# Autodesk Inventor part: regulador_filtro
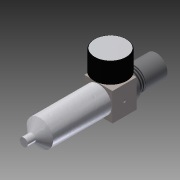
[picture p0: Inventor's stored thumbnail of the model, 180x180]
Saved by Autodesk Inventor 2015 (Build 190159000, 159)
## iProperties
Created: 2016-06
Part Number: regulador_filtro
Material: Genérico
Document SubType Name: Modeling
Designer: Diego
Density: 1 g/cm^3
Appearance: Valor por defecto
Author: Diego
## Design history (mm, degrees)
sketch "Boceto1"
  geometry: L1 (0, 0)-(35, 0); L2 (35, 0)-(35, 30); L3 (35, 30)-(0, 30); L4 (0, 30)-(0, 0)
  constraints: 8 end point, 2 parallel, 1 horizontal, 1 perpendicular
  dimensions: "d0" = 35 distance of L3.end L2.end; "d1" = 30 distance of L2.end L1.end
extrude "Extrusión1" new body sketch "Boceto1" distance "d2" = 35; taper "d3" = 0 deg
sketch "Boceto2"
  geometry: C1 r 17.534 at (17.5, -17.5); 1 further point
  constraints: 1 centre point
extrude "Extrusión2" join sketch "Boceto2" distance "d4" = 5; taper "d5" = 0 deg
sketch "Boceto3"
  geometry: C1 r 13.5 at (0, 0); 1 further point
  constraints: 1 centre point
  dimensions: "d6" = 27 diameter of C1
extrude "Extrusión3" join sketch "Boceto3" distance "d7" = 10; taper "d8" = 0 deg
feature "Rosca1" dims "d9" = 10, "d10" = 0
sketch "Boceto4"
  geometry: C1 r 14 at (0, 0); 1 further point
  constraints: 1 centre point
  dimensions: "d11" = 28 diameter of C1
extrude "Extrusión4" join sketch "Boceto4" distance "d12" = 27; taper "d13" = 0 deg
sketch "Boceto5"
  geometry: C1 r 5 at (17.5, 15); 1 further point
  constraints: 1 centre point
  dimensions: "d14" = 10 diameter of C1
extrude "Extrusión5" join sketch "Boceto5" distance "d15" = 5; taper "d16" = 0 deg
sketch "Boceto6"
  geometry: C1 r 20.5 at (0, 0); 1 further point
  constraints: 1 centre point
  dimensions: "d17" = 41 diameter of C1
extrude "Extrusión6" join sketch "Boceto6" distance "d18" = 25; taper "d19" = 0 deg
sketch "Boceto7"
  geometry: C1 r 20.5 at (0, 0) reference; C2 r 19.5 at (0, 0); 1 further point
  constraints: 1 centre point
  dimensions: "d20" = 1 radial gap between concentric circles of C1 C2
extrude "Extrusión7" join sketch "Boceto7" distance "d21" = 2; taper "d22" = 0 deg
fillet "Empalme1" dims "d23" = 2
sketch "Boceto8"
  geometry: 2 further points
hole "Agujero1" sketch "Boceto8" at (16.415, 15) diameter "d24" = 3; stored, may be unused: countersink angle "d28" = 90 deg, drill point angle "d30" = 118 deg; dims "d25" = 6, "d26" = 4, "d27" = 2, "d29" = 1
sketch "Boceto9"
  geometry: 2 further points
hole "Agujero2" sketch "Boceto9" at (-16.415, 15) diameter "d31" = 3; stored, may be unused: countersink angle "d35" = 90 deg, drill point angle "d37" = 118 deg; dims "d32" = 6, "d33" = 4, "d34" = 2, "d36" = 1
sketch "Boceto10"
  geometry: C1 r 13.5 at (17.5, 17.5) reference; C2 r 16.5 at (17.5, 17.5); 1 further point
  constraints: 1 centre point, 1 coincident
  dimensions: "d38" = 33 diameter of C2
extrude "Extrusión8" join sketch "Boceto10" distance "d39" = 73; taper "d40" = 0 deg
node "Plano de trabajo1"
sketch "Boceto11"
  geometry: C1 r 16.5 at (0, 0) reference; C2 r 5 at (0, 0); 1 further point
  constraints: 1 centre point, 1 coincident
  dimensions: "d42" = 10 diameter of C2
feature "Solevación1" sketch "Boceto11" dims "d43" = 0, "d44" = 90 deg, "d45" = 0, "d46" = 90 deg
  node "Aristas1"
sketch "Boceto12"
  geometry: C1 r 5 at (0, 0); 1 further point
  constraints: 1 centre point
  dimensions: "d47" = 10 diameter of C1
extrude "Extrusión9" join sketch "Boceto12" distance "d48" = 10; taper "d49" = 0 deg
node "Sólido1"
